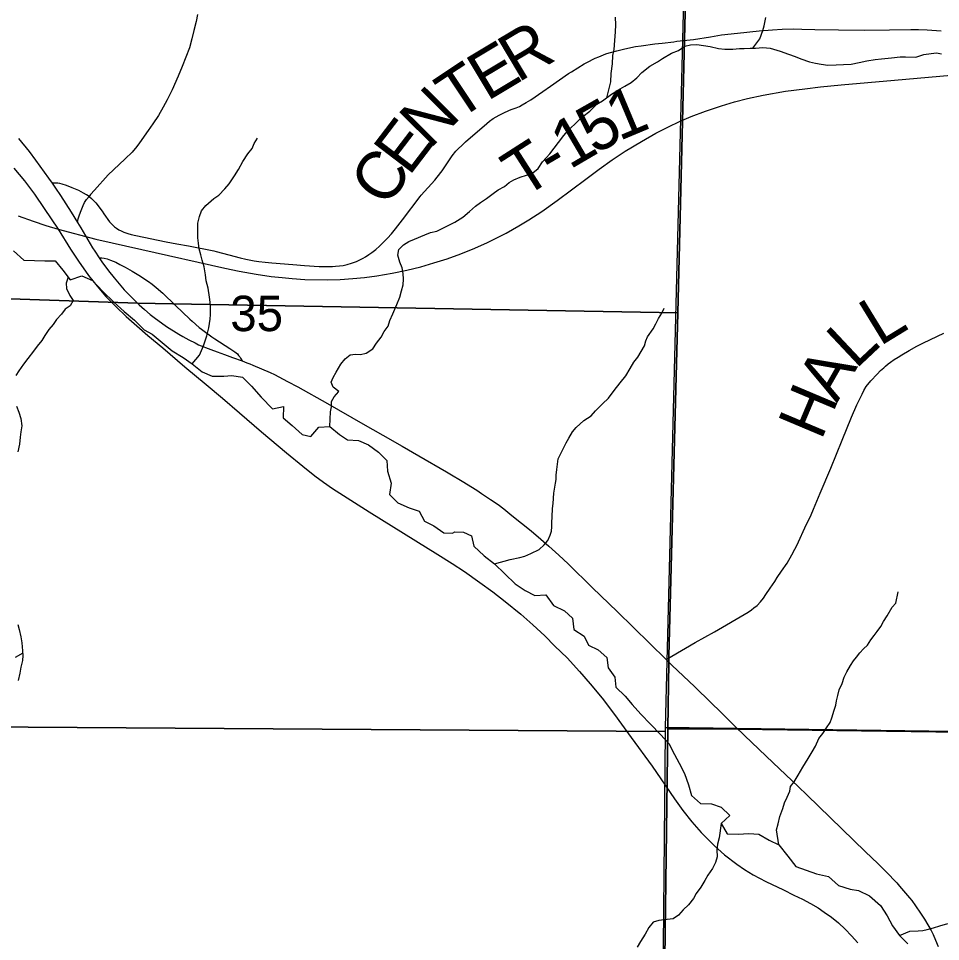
# Model space of a CAD drawing. Extents: x 0 to 34, y 0 to 22.
# Drawn here: x 15.702 to 16.791, y 16.673 to 17.764 of the extents above; entities that cross this region are included whole.
import ezdxf

# ---------------------------------------------------------------- set-up
doc = ezdxf.new("R2010")
doc.units = 0
for name, color, linetype in [('GM_X_Corporation', 7, 'Continuous'), ('GM_X_Major_River', 7, 'Continuous'), ('GM_X_Minor_River', 7, 'Continuous'), ('GM_X_Rail_Line', 7, 'Continuous'), ('GM_X_Section_Text', 7, 'Continuous'), ('GM_X_State_Route', 7, 'Continuous'), ('GM_X_Township_Road', 7, 'Continuous'), ('GM_X_Township_Road_Text', 7, 'Continuous')]:
    doc.layers.add(name, color=color, linetype=linetype)

msp = doc.modelspace()

# ---------------------------------------------------------------- linework, layer by layer
at = {"layer": 'GM_X_Corporation'}
for points in [[(13.2742, 17.4966), (14.0954, 17.4811), (14.726, 17.4654), (14.7561, 17.4645), (15.8426, 17.4278), (15.8844, 17.4269), (16.4807, 17.4161), (16.4886, 17.7392), (16.5168, 18.8707), (16.5174, 18.8935), (16.5475, 18.8929), (16.752, 18.8891), (16.7532, 19.0614), (16.7547, 19.2837), (16.7652, 20.328), (16.7661, 20.4), (11.5001, 20.4)], [(16.4419, 14.8642), (16.4498, 15.4626), (16.4516, 15.5964), (16.4611, 16.1288), (16.4603, 16.2617), (16.4689, 16.9245), (16.4703, 17.0036), (16.4704, 17.0104), (16.4807, 17.4161), (15.8844, 17.4269), (15.8426, 17.4278), (14.7561, 17.4645), (14.726, 17.4654), (14.0954, 17.4811), (13.2742, 17.4966)]]:
    msp.add_lwpolyline(points, dxfattribs=at)
for points in [[(17.4, 16.913), (17.4, 20.4), (16.7661, 20.4), (16.7652, 20.328), (16.7547, 19.2837), (16.7532, 19.0614), (16.752, 18.8891), (16.5475, 18.8929), (16.5174, 18.8935), (16.5168, 18.8707), (16.4886, 17.7392), (16.4807, 17.4161), (16.4704, 17.0104), (16.4703, 17.0036), (16.4689, 16.9245), (16.5516, 16.9243)], [(15.5004, 17.9447), (16.4906, 17.9114), (16.466, 16.9263), (16.466, 16.9214), (15.4816, 16.9282)], [(17.4, 16.9134), (17.4, 17.9189), (16.4906, 17.9114), (16.466, 16.9263)], [(15.4816, 16.9282), (16.466, 16.9214), (16.4563, 15.9084), (15.4691, 15.9163)], [(16.4214, 13.6), (17.4, 13.6), (17.4, 16.913), (16.5516, 16.9243), (16.4689, 16.9245), (16.4603, 16.2617), (16.4611, 16.1288), (16.4516, 15.5964), (16.4498, 15.4626), (16.4419, 14.8642), (16.438, 14.5908), (16.4339, 14.3806), (16.4212, 13.6609)], [(17.4, 15.8967), (17.4, 16.9134), (16.466, 16.9263), (16.466, 16.9214), (16.4563, 15.9084)]]:
    msp.add_lwpolyline(points, close=True, dxfattribs=at)
at = {"layer": 'GM_X_Major_River'}
for points in [[(15.6963, 17.4896), (15.7085, 17.4784), (15.7211, 17.4782), (15.7332, 17.4776), (15.7454, 17.4778), (15.7546, 17.4665), (15.7631, 17.4553), (15.7768, 17.46), (15.7894, 17.4545), (15.8017, 17.4414), (15.8147, 17.429), (15.827, 17.4178), (15.8393, 17.4074), (15.8505, 17.3961), (15.86, 17.391), (15.8719, 17.3813), (15.8835, 17.3712), (15.8965, 17.3634), (15.9072, 17.3559), (15.9191, 17.3466), (15.9309, 17.3415), (15.9446, 17.3413), (15.9541, 17.3422), (15.9666, 17.3401), (15.9774, 17.3296), (15.9886, 17.3165)], [(15.9886, 17.3165), (16.0021, 17.3026), (16.0153, 17.3055), (16.0147, 17.2922), (16.0255, 17.2832), (16.037, 17.2724), (16.0473, 17.2699), (16.057, 17.281), (16.0699, 17.2819), (16.0811, 17.2726), (16.0906, 17.2663), (16.1039, 17.2653), (16.1154, 17.2602), (16.1273, 17.2516), (16.1373, 17.2419), (16.1378, 17.229), (16.1422, 17.215), (16.1405, 17.2017), (16.1501, 17.1916), (16.1634, 17.1857), (16.1753, 17.1817), (16.1815, 17.17), (16.1926, 17.1645), (16.2045, 17.1563), (16.2147, 17.156)], [(16.2147, 17.156), (16.2173, 17.1576), (16.2276, 17.157), (16.2372, 17.1526), (16.24, 17.1405), (16.2523, 17.1292), (16.2645, 17.1195), (16.2888, 17.096), (16.3006, 17.0882), (16.3121, 17.0823), (16.325, 17.0828), (16.3339, 17.0704), (16.3469, 17.0641), (16.3565, 17.0556), (16.3582, 17.0419), (16.3701, 17.0341), (16.3755, 17.0236), (16.3866, 17.018), (16.397, 17.0091), (16.3987, 16.9966), (16.4064, 16.9857), (16.4077, 16.9739), (16.4185, 16.9631), (16.427, 16.9533), (16.437, 16.9421), (16.4485, 16.9301), (16.4604, 16.9181), (16.4701, 16.9072), (16.4771, 16.8944), (16.4825, 16.8839), (16.4888, 16.8718), (16.4935, 16.8586), (16.4971, 16.8457), (16.5078, 16.8364), (16.5208, 16.8362), (16.5322, 16.8322), (16.5422, 16.8221), (16.5321, 16.8128), (16.5391, 16.8004), (16.552, 16.8002), (16.5649, 16.8008), (16.5767, 16.8002), (16.5889, 16.7931), (16.6, 16.7876), (16.6108, 16.7741), (16.6204, 16.7621), (16.6326, 16.7577), (16.6445, 16.7533), (16.6589, 16.7501), (16.6708, 16.7396), (16.6846, 16.7352), (16.6941, 16.7335), (16.7071, 16.7272), (16.7201, 16.716), (16.7283, 16.7036), (16.7345, 16.6919), (16.7426, 16.6806), (16.7526, 16.6705)]]:
    msp.add_lwpolyline(points, dxfattribs=at)
at = {"layer": 'GM_X_Minor_River'}
for points in [[(16.3969, 17.6704), (16.4017, 17.6893), (16.4023, 17.6992), (16.4036, 17.7106), (16.4042, 17.7205), (16.4056, 17.7274), (16.4065, 17.738), (16.4071, 17.7483), (16.4077, 17.7567), (16.4072, 17.7658)], [(16.5694, 17.7291), (16.573, 17.7337), (16.5778, 17.7402), (16.5811, 17.7498), (16.5829, 17.7555), (16.585, 17.7654)], [(16.0699, 17.2819), (16.0706, 17.2991), (16.072, 17.3052), (16.0719, 17.3113), (16.0748, 17.3171), (16.0804, 17.3232), (16.0739, 17.3284), (16.0715, 17.3341), (16.0737, 17.3398), (16.0774, 17.346), (16.0829, 17.3556), (16.0881, 17.3617), (16.0937, 17.3664), (16.1001, 17.3673), (16.1062, 17.367), (16.1126, 17.3686), (16.1205, 17.3737), (16.1249, 17.3802), (16.1305, 17.3875), (16.1342, 17.3941), (16.1386, 17.4006), (16.1408, 17.4071), (16.1444, 17.4151), (16.1488, 17.4259), (16.1524, 17.4347), (16.1546, 17.4423), (16.1563, 17.4492), (16.157, 17.456), (16.1565, 17.4628), (16.1552, 17.4693), (16.1525, 17.4761), (16.1501, 17.4844), (16.1515, 17.4909), (16.1567, 17.4966), (16.1631, 17.5006), (16.1698, 17.5033), (16.1819, 17.5085), (16.1886, 17.5113), (16.1962, 17.5129), (16.2048, 17.5169), (16.2176, 17.5235), (16.227, 17.5294), (16.2348, 17.536), (16.2419, 17.5422), (16.2479, 17.5465), (16.2547, 17.5515), (16.2629, 17.5574), (16.2685, 17.5616), (16.276, 17.5656), (16.2816, 17.5702), (16.2873, 17.5734), (16.2948, 17.5765), (16.302, 17.5789), (16.3095, 17.5817), (16.3159, 17.5868), (16.321, 17.5948), (16.3296, 17.6041), (16.34, 17.6176), (16.3463, 17.6257), (16.3515, 17.6318), (16.3627, 17.6427), (16.3686, 17.6481), (16.3769, 17.6547), (16.3854, 17.6628), (16.3918, 17.6667), (16.4027, 17.6745), (16.4128, 17.6808), (16.4184, 17.6839), (16.4256, 17.6886), (16.4323, 17.694), (16.4382, 17.7002), (16.448, 17.7076), (16.457, 17.7127), (16.4626, 17.7166), (16.4735, 17.7232), (16.4818, 17.7264), (16.4893, 17.7315), (16.4957, 17.7331), (16.5033, 17.7332), (16.5192, 17.7309), (16.5291, 17.7284), (16.5363, 17.7277), (16.5458, 17.7279), (16.5538, 17.7284), (16.5594, 17.7285), (16.5662, 17.729), (16.5727, 17.7291), (16.5814, 17.7297), (16.5901, 17.729), (16.6016, 17.7254), (16.6115, 17.7218), (16.6195, 17.7193), (16.6263, 17.7164), (16.6363, 17.7128), (16.6435, 17.7114), (16.65, 17.7099), (16.6579, 17.7089), (16.6678, 17.7091), (16.6765, 17.7096), (16.6856, 17.7102), (16.695, 17.7122)], [(16.695, 17.7122), (16.7041, 17.7139), (16.7139, 17.7156), (16.7215, 17.7165), (16.7332, 17.7175), (16.7434, 17.7188), (16.7499, 17.7189), (16.762, 17.7183), (16.7714, 17.7215), (16.7801, 17.7225), (16.7866, 17.7233), (16.7923, 17.7223)], [(15.9072, 17.3559), (15.9159, 17.3663), (15.9207, 17.3771), (15.9246, 17.3889), (15.9268, 17.3984), (15.9285, 17.4087), (15.9288, 17.4144), (15.929, 17.4217), (15.9285, 17.4289), (15.9277, 17.4349), (15.9263, 17.4452), (15.9239, 17.4542), (15.923, 17.4611), (15.9214, 17.4705), (15.919, 17.4785), (15.9173, 17.4849), (15.9157, 17.4917), (15.9148, 17.4985), (15.914, 17.505), (15.9138, 17.5156), (15.914, 17.5221), (15.9158, 17.5301), (15.9183, 17.5369), (15.9235, 17.5431), (15.9329, 17.5513), (15.9389, 17.5552), (15.9459, 17.5629), (15.9508, 17.5687), (15.9571, 17.5783), (15.9619, 17.5856), (15.967, 17.5952), (15.9729, 17.604), (15.9781, 17.6105), (15.9803, 17.6163), (15.9843, 17.6228)], [(15.7607, 17.4585), (15.7583, 17.4514), (15.7588, 17.4449), (15.7627, 17.4366), (15.7666, 17.4306), (15.763, 17.4245), (15.7573, 17.4206), (15.7529, 17.4148), (15.7469, 17.4082), (15.7429, 17.4025), (15.738, 17.3967), (15.7332, 17.3894), (15.7295, 17.3836), (15.724, 17.3767), (15.7199, 17.3709), (15.7132, 17.3624), (15.708, 17.3555), (15.7025, 17.3478), (15.6988, 17.3421)], [(16.2645, 17.1195), (16.2828, 17.1247), (16.2941, 17.1271), (16.3001, 17.1288), (16.3073, 17.1319), (16.3171, 17.1367), (16.323, 17.1421), (16.3275, 17.1471), (16.33, 17.1536), (16.3315, 17.1582), (16.3321, 17.1635), (16.3321, 17.1684), (16.3323, 17.1753), (16.3329, 17.1852), (16.3336, 17.1909), (16.3345, 17.2031), (16.3362, 17.2149), (16.3373, 17.2194), (16.3372, 17.2244), (16.3378, 17.2312), (16.3395, 17.2438), (16.3457, 17.2564), (16.349, 17.2626), (16.352, 17.2683), (16.3564, 17.2756), (16.3609, 17.2806), (16.3698, 17.2891), (16.3784, 17.2946), (16.3836, 17.3004), (16.3918, 17.3085), (16.3989, 17.3155), (16.4056, 17.3243), (16.4126, 17.3336), (16.4193, 17.3417), (16.4245, 17.3505), (16.4289, 17.3578), (16.4337, 17.3639), (16.4415, 17.3774), (16.4429, 17.3831), (16.4451, 17.3877), (16.4517, 17.3973), (16.455, 17.4031), (16.458, 17.4096), (16.462, 17.4157), (16.4646, 17.4218)], [(15.6998, 17.306), (15.7025, 17.2988), (15.705, 17.2913), (15.7059, 17.2825), (15.7048, 17.2757), (15.7042, 17.2692), (15.7032, 17.2612), (15.7014, 17.2521)], [(16.6, 16.7876), (16.5975, 16.8053), (16.5993, 16.8122), (16.6014, 16.821), (16.605, 16.8305), (16.6068, 16.837), (16.6101, 16.8439), (16.613, 16.8508), (16.6141, 16.8565), (16.6181, 16.8619), (16.6229, 16.87), (16.6285, 16.8792), (16.6347, 16.8895), (16.6395, 16.8976), (16.6436, 16.9041), (16.6476, 16.9133), (16.652, 16.9191), (16.6565, 16.926), (16.6609, 16.9322), (16.6627, 16.9375), (16.6656, 16.9467), (16.6674, 16.9528), (16.6684, 16.9577), (16.6698, 16.9639), (16.6716, 16.9707), (16.6749, 16.9784), (16.6774, 16.9856), (16.6804, 16.9921), (16.6848, 16.9994), (16.6885, 17.0048), (16.6918, 17.0094), (16.6959, 17.0144), (16.7, 17.0191), (16.7048, 17.0237), (16.7089, 17.0299), (16.7126, 17.0349), (16.7163, 17.0395), (16.7208, 17.0456), (16.7237, 17.0514), (16.7281, 17.0583), (16.734, 17.0683), (16.7385, 17.0733), (16.7413, 17.0866)], [(15.7015, 17.0481), (15.7031, 17.042), (15.7048, 17.0333), (15.706, 17.0261), (15.707, 17.017), (15.7074, 17.0114), (15.7068, 17.0053), (15.705, 16.9976), (15.7036, 16.9904), (15.7019, 16.9816)], [(15.7072, 17.014), (15.698, 17.0089)], [(16.5321, 16.8128), (16.5298, 16.7958), (16.5277, 16.7882), (16.527, 16.7817), (16.5275, 16.7734), (16.5254, 16.7665), (16.5217, 16.7596), (16.5162, 16.7519), (16.5129, 16.7454), (16.5081, 16.7377), (16.5025, 16.73), (16.4992, 16.7242), (16.4933, 16.7165), (16.4873, 16.7107), (16.4817, 16.7046), (16.4753, 16.7003), (16.4682, 16.6994), (16.4583, 16.6981), (16.4519, 16.6961), (16.4467, 16.6899), (16.4423, 16.6818), (16.4368, 16.6734), (16.4327, 16.6665)], [(16.7426, 16.6806), (16.7549, 16.6854), (16.7648, 16.6859), (16.7701, 16.6864), (16.7754, 16.6876), (16.7829, 16.6893), (16.7905, 16.6917), (16.7999, 16.6945)]]:
    msp.add_lwpolyline(points, dxfattribs=at)
at = {"layer": 'GM_X_Rail_Line'}
for points in [[(15.7017, 17.531), (15.7196, 17.5246), (15.7345, 17.5194), (15.7488, 17.5149), (15.7935, 17.5032), (15.8478, 17.4909), (15.9458, 17.4692), (15.9626, 17.4656), (15.983, 17.462), (16.0006, 17.4593), (16.0135, 17.4578), (16.0252, 17.4566), (16.0402, 17.4557), (16.0671, 17.4554), (16.0822, 17.4558), (16.0969, 17.4568), (16.1109, 17.4581), (16.1253, 17.4601), (16.1434, 17.463), (16.1608, 17.4666), (16.1772, 17.4706), (16.1928, 17.4753), (16.2084, 17.4802), (16.2247, 17.4859), (16.2411, 17.4925), (16.2562, 17.4993), (16.278, 17.5104), (16.2932, 17.519), (16.3049, 17.5261), (16.3201, 17.5361), (16.3382, 17.5489), (16.3724, 17.5743), (16.388, 17.586), (16.4033, 17.597), (16.4187, 17.6074), (16.4379, 17.6188), (16.455, 17.6284), (16.4698, 17.6362), (16.4829, 17.6423), (16.4968, 17.6482), (16.5136, 17.6544), (16.5324, 17.6609), (16.5478, 17.6654), (16.5633, 17.6694), (16.5817, 17.6735), (16.608, 17.678), (16.6307, 17.681), (16.6492, 17.6832), (16.6739, 17.6855), (16.7367, 17.6911), (16.8171, 17.6981)], [(15.6968, 17.5871), (15.7092, 17.5723), (15.7212, 17.5565), (15.7325, 17.5397), (15.7488, 17.5149), (15.7635, 17.4913), (15.7728, 17.4774), (15.7848, 17.4605), (15.7949, 17.4478), (15.8053, 17.4356), (15.8171, 17.4237), (15.8294, 17.412), (15.8419, 17.4009), (15.855, 17.3895), (15.8725, 17.375), (15.8987, 17.3526), (15.9236, 17.3316), (15.943, 17.3152), (15.9632, 17.2979), (15.9893, 17.2756), (16.0185, 17.2509), (16.0378, 17.2351), (16.0521, 17.2238), (16.0623, 17.2163), (16.0731, 17.2087), (16.1162, 17.1809), (16.1716, 17.1468), (16.1974, 17.1308), (16.2144, 17.12), (16.2289, 17.1106), (16.2472, 17.0974), (16.2624, 17.0865), (16.2769, 17.0751), (16.2954, 17.0601), (16.3098, 17.0474), (16.3236, 17.0345), (16.3358, 17.0224), (16.35, 17.0084), (16.3647, 16.9923), (16.3775, 16.9778), (16.3914, 16.9608), (16.4061, 16.9417), (16.4257, 16.9145), (16.4504, 16.8804), (16.4771, 16.8418), (16.4866, 16.8283), (16.4974, 16.8148), (16.5084, 16.802), (16.5241, 16.7863), (16.5359, 16.7759), (16.5504, 16.7647), (16.5598, 16.7585), (16.57, 16.7523), (16.5848, 16.7443), (16.6055, 16.7343), (16.618, 16.7282), (16.6282, 16.7233), (16.6377, 16.7182), (16.6465, 16.7131), (16.6539, 16.708), (16.6624, 16.702), (16.6708, 16.6952), (16.6786, 16.6881), (16.686, 16.6802), (16.6935, 16.6716)]]:
    msp.add_lwpolyline(points, dxfattribs=at)
at = {"layer": 'GM_X_State_Route'}
for points in [[(15.702, 17.6221), (15.7146, 17.6067), (15.7221, 17.5967), (15.7326, 17.5824), (15.7377, 17.5754), (15.7419, 17.5696), (15.7459, 17.5636), (15.7518, 17.5547), (15.7644, 17.5353), (15.7718, 17.5231), (15.7757, 17.5168), (15.7894, 17.4931), (15.7921, 17.4889), (15.7973, 17.4814), (15.8007, 17.4765), (15.8086, 17.466), (15.815, 17.4576), (15.821, 17.4505), (15.8271, 17.4434), (15.8313, 17.439), (15.8406, 17.4295), (15.8448, 17.4256)], [(15.8448, 17.4256), (15.8509, 17.4201), (15.8578, 17.4143), (15.8641, 17.4094), (15.8709, 17.4044), (15.877, 17.4001), (15.8914, 17.3909), (15.8961, 17.3882), (15.9034, 17.3843), (15.9107, 17.3806), (15.9149, 17.3786), (15.9292, 17.3729), (15.9367, 17.37), (15.9456, 17.3669), (15.955, 17.3635), (15.9662, 17.3595), (15.9717, 17.3573), (15.9752, 17.3559), (15.9789, 17.3544), (15.9992, 17.3456), (16.0043, 17.3433), (16.0199, 17.3352), (16.0322, 17.3286), (16.0669, 17.3092), (16.109, 17.2852), (16.1326, 17.2717), (16.1551, 17.2587), (16.1749, 17.2473), (16.2075, 17.2284), (16.2117, 17.2259), (16.2261, 17.2172), (16.2436, 17.2065), (16.2489, 17.2029), (16.2598, 17.1957), (16.2687, 17.1897), (16.2754, 17.1847), (16.285, 17.1769), (16.2963, 17.1678), (16.3076, 17.1585), (16.3192, 17.1486), (16.3284, 17.1406), (16.3404, 17.1297), (16.3513, 17.1196), (16.3801, 17.0914), (16.4092, 17.0631), (16.4672, 17.0065), (16.4738, 16.9999)], [(16.4738, 16.9999), (16.5009, 16.9742), (16.5199, 16.9557), (16.5316, 16.9444), (16.5397, 16.9364), (16.5488, 16.9273), (16.5596, 16.9168)], [(16.5596, 16.9168), (16.5935, 16.8844), (16.6232, 16.8563), (16.6336, 16.8462), (16.7022, 16.7798), (16.7174, 16.7652), (16.7268, 16.7558), (16.7394, 16.7425), (16.7429, 16.7387), (16.7545, 16.7249), (16.7572, 16.7216), (16.7618, 16.7154), (16.7675, 16.707), (16.7723, 16.6997), (16.7762, 16.6932), (16.78, 16.6864), (16.7824, 16.6816), (16.7854, 16.675), (16.7885, 16.6675)]]:
    msp.add_lwpolyline(points, dxfattribs=at)
at = {"layer": 'GM_X_Township_Road'}
msp.add_line((16.4672, 17.0065), (16.4738, 17.0105), dxfattribs=at)
for points in [[(15.9136, 17.7686), (15.912, 17.7604), (15.9094, 17.7499), (15.9068, 17.7402), (15.9039, 17.7295), (15.8998, 17.7184), (15.8956, 17.7072), (15.8907, 17.696), (15.8837, 17.6798), (15.8778, 17.668), (15.8731, 17.6593), (15.8674, 17.6496), (15.8609, 17.6396), (15.8553, 17.6318), (15.845, 17.617), (15.8417, 17.6126), (15.8365, 17.6061), (15.8283, 17.5982), (15.821, 17.5915), (15.808, 17.5792), (15.792, 17.5612)], [(16.4798, 17.7371), (16.4995, 17.7394), (16.5195, 17.7425), (16.5326, 17.7447), (16.5514, 17.7468), (16.5769, 17.7496), (16.5927, 17.7508), (16.6042, 17.7513), (16.6173, 17.7517), (16.6275, 17.7516), (16.6427, 17.7512), (16.6707, 17.7507), (16.7013, 17.7503), (16.731, 17.7508), (16.756, 17.7512), (16.765, 17.7511), (16.7753, 17.7508), (16.7918, 17.7496)], [(15.792, 17.5612), (15.7873, 17.556), (15.7854, 17.5536), (15.7883, 17.5515), (15.7893, 17.5506), (15.792, 17.5479), (15.7934, 17.5462), (15.8009, 17.5364), (15.8031, 17.5331), (15.8096, 17.5239), (15.8107, 17.5225), (15.813, 17.5201), (15.8155, 17.5179), (15.8177, 17.5163), (15.8206, 17.5145), (15.8233, 17.5131), (15.8264, 17.5117), (15.8312, 17.51), (15.8351, 17.5088), (15.8406, 17.5075), (15.8767, 17.5002), (15.8892, 17.4978), (15.9029, 17.4952), (15.9328, 17.4894), (15.9357, 17.4887), (15.9505, 17.4846), (15.9639, 17.4812), (15.9705, 17.4797), (15.9805, 17.4778), (15.9858, 17.477), (15.9933, 17.476), (16.0013, 17.4753), (16.026, 17.4733), (16.0398, 17.4722), (16.0574, 17.4711), (16.0621, 17.4709), (16.0728, 17.4709), (16.0764, 17.4712), (16.0811, 17.4716), (16.0855, 17.4723), (16.0904, 17.4734), (16.0955, 17.4749), (16.1013, 17.477), (16.1045, 17.4784), (16.1091, 17.4807), (16.1121, 17.4824), (16.1161, 17.485), (16.1196, 17.4876), (16.124, 17.4912), (16.1285, 17.4951), (16.1334, 17.4997), (16.1379, 17.5043), (16.1426, 17.5097), (16.1475, 17.5156), (16.1558, 17.5263), (16.1765, 17.5536), (16.1779, 17.5553), (16.1939, 17.573), (16.1967, 17.5765), (16.2025, 17.5842), (16.2049, 17.5876), (16.2127, 17.5995), (16.2143, 17.6016), (16.2188, 17.6071), (16.2207, 17.6092), (16.2268, 17.6152), (16.23, 17.6181), (16.2553, 17.6401), (16.2586, 17.6427), (16.2629, 17.6458), (16.2662, 17.6479), (16.2699, 17.6499), (16.2744, 17.6522), (16.2822, 17.6556), (16.2852, 17.6567), (16.29, 17.6586), (16.2938, 17.6602), (16.2972, 17.662), (16.3017, 17.6646), (16.3073, 17.6681), (16.3213, 17.6776), (16.3303, 17.684), (16.3518, 17.6989), (16.3552, 17.7012), (16.3701, 17.7103), (16.3735, 17.7122), (16.3831, 17.717), (16.3876, 17.7189), (16.396, 17.7223), (16.3998, 17.7235), (16.4089, 17.726), (16.4181, 17.7281), (16.431, 17.7308), (16.4375, 17.7318), (16.4538, 17.7341), (16.4624, 17.735), (16.4761, 17.7366), (16.4798, 17.7371)], [(15.7718, 17.5231), (15.7727, 17.5272), (15.7742, 17.532), (15.7761, 17.537), (15.7785, 17.543), (15.7802, 17.5466), (15.7824, 17.5501), (15.7854, 17.5536), (15.7823, 17.5555), (15.7789, 17.5576), (15.7732, 17.5606), (15.7655, 17.5639), (15.7587, 17.5667), (15.7538, 17.5683), (15.7508, 17.569), (15.7484, 17.5693), (15.746, 17.5695), (15.7419, 17.5696)], [(15.7973, 17.4814), (15.8004, 17.4813), (15.8032, 17.4809), (15.8067, 17.48), (15.8107, 17.4785), (15.8172, 17.4759), (15.8219, 17.4735), (15.8283, 17.4702), (15.8363, 17.4656), (15.8441, 17.4609), (15.8557, 17.4533), (15.8601, 17.4501), (15.8648, 17.4462), (15.8724, 17.4393), (15.8877, 17.4248)], [(15.8877, 17.4248), (15.9045, 17.4089), (15.9072, 17.4063), (15.9157, 17.399), (15.9182, 17.397), (15.9305, 17.388), (15.9339, 17.3856), (15.9516, 17.3741), (15.9576, 17.3702), (15.9591, 17.3689), (15.9606, 17.3677), (15.9621, 17.366), (15.9636, 17.3642), (15.9645, 17.3628), (15.9662, 17.3595)], [(16.4738, 17.0105), (16.5014, 17.0267), (16.5242, 17.0393), (16.5638, 17.0626), (16.5677, 17.0653), (16.5706, 17.0675), (16.5744, 17.0705), (16.5785, 17.0748), (16.5819, 17.079), (16.585, 17.0834), (16.5901, 17.0909), (16.5955, 17.0989), (16.5984, 17.1035), (16.6034, 17.1109), (16.6099, 17.1204), (16.6155, 17.1304), (16.6191, 17.1369), (16.6215, 17.1413), (16.6236, 17.1458), (16.6308, 17.162), (16.6382, 17.1777), (16.641, 17.1843), (16.649, 17.2031), (16.6615, 17.2327), (16.6751, 17.2657), (16.6859, 17.2928), (16.6925, 17.3074), (16.6985, 17.32), (16.7006, 17.3243), (16.7035, 17.329), (16.709, 17.3358), (16.7163, 17.3439), (16.7203, 17.348), (16.7241, 17.3514), (16.7261, 17.3532), (16.7292, 17.3558), (16.7319, 17.3579), (16.7365, 17.361), (16.741, 17.3639), (16.7455, 17.3667), (16.754, 17.3719), (16.7632, 17.3769), (16.7712, 17.3809), (16.7949, 17.3922)]]:
    msp.add_lwpolyline(points, dxfattribs=at)

# ---------------------------------------------------------------- texts
at = {"layer": 'GM_X_Section_Text'}
msp.add_text('35', height=0.04186, rotation=0, dxfattribs=at).set_placement((15.9523, 17.3946))
at = {"layer": 'GM_X_Township_Road_Text'}
for s, rotation, p in [('R', 30.7877, (16.2919, 17.6876)), ('E', 30.916, (16.2555, 17.6657)), ('T', 33.6592, (16.2207, 17.6426)), ('N', 45.2086, (16.1878, 17.609)), ('1', 22.7454, (16.4113, 17.6189)), ('5', 29.6712, (16.3828, 17.6025)), ('E', 52.6595, (16.1633, 17.5767)), ('1', 30.416, (16.353, 17.585)), ('T', 32.6751, (16.2979, 17.5507)), ('C', 54.8874, (16.1368, 17.539)), ('-', 30.5607, (16.3331, 17.5733)), ('L', 31.4966, (16.7193, 17.3761)), ('L', 43.236, (16.6908, 17.3488)), ('A', 60.3283, (16.6688, 17.3089)), ('H', 67.1209, (16.6502, 17.2644))]:
    msp.add_text(s, height=0.0568, rotation=rotation, dxfattribs=at).set_placement(p)

doc.saveas('drawing.dxf')
